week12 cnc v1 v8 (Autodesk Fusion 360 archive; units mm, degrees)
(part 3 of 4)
sketch "Sketch43" plane through (0, 0, 0) normal (0, 0, 1) x axis (1, 0, 0)
  line L1 (2935.833, 1472.2699) -> (497.833, 1472.2699)
  line L2 (497.833, 1472.2699) -> (497.833, 2691.2699)
  line L3 (497.833, 2691.2699) -> (2935.833, 2691.2699)
  line L4 (2935.833, 2691.2699) -> (2935.833, 1472.2699)
  line L5 (1708.427, 1904.6779) -> (1708.427, 1833.235)
  line L6 (1720.427, 1908.9564) -> (1712.7056, 1908.9564)
  line L7 (1720.427, 1971.9564) -> (1720.427, 1908.9564)
  line L8 (1684.7056, 1971.9564) -> (1720.427, 1971.9564)
  line L9 (1680.427, 1983.9564) -> (1680.427, 1976.235)
  line L10 (1626.7841, 1983.9564) -> (1680.427, 1983.9564)
  line L11 (1626.7841, 1976.235) -> (1626.7841, 1983.9564)
  line L12 (1591.0627, 1971.9564) -> (1622.5056, 1971.9564)
  line L13 (1586.7841, 1983.9564) -> (1586.7841, 1976.235)
  line L14 (1533.1413, 1983.9564) -> (1586.7841, 1983.9564)
  line L15 (1533.1413, 1976.235) -> (1533.1413, 1983.9564)
  line L16 (1497.4198, 1971.9564) -> (1528.8627, 1971.9564)
  line L17 (1493.1413, 1983.9564) -> (1493.1413, 1976.235)
  line L18 (1439.4984, 1983.9564) -> (1493.1413, 1983.9564)
  line L19 (1439.4984, 1976.235) -> (1439.4984, 1983.9564)
  line L20 (1403.777, 1971.9564) -> (1435.2199, 1971.9564)
  line L21 (1399.4984, 1983.9564) -> (1399.4984, 1976.235)
  line L22 (1345.8556, 1983.9564) -> (1399.4984, 1983.9564)
  line L23 (1345.8556, 1976.235) -> (1345.8556, 1983.9564)
  line L24 (1310.1341, 1971.9564) -> (1341.577, 1971.9564)
  line L25 (1305.8556, 1983.9564) -> (1305.8556, 1976.235)
  line L26 (1252.2127, 1983.9564) -> (1305.8556, 1983.9564)
  line L27 (1252.2127, 1976.235) -> (1252.2127, 1983.9564)
  line L28 (1216.4913, 1971.9564) -> (1247.9342, 1971.9564)
  line L29 (1212.2127, 1983.9564) -> (1212.2127, 1976.235)
  line L30 (1158.5699, 1983.9564) -> (1212.2127, 1983.9564)
  line L31 (1158.5699, 1976.235) -> (1158.5699, 1983.9564)
  line L32 (1122.8484, 1971.9564) -> (1154.2913, 1971.9564)
  line L33 (1118.5699, 1983.9564) -> (1118.5699, 1976.235)
  line L34 (1064.927, 1983.9564) -> (1118.5699, 1983.9564)
  line L35 (1064.927, 1976.235) -> (1064.927, 1983.9564)
  line L36 (1025, 1971.9564) -> (1060.6484, 1971.9564)
  line L37 (1025, 1908.9564) -> (1025, 1971.9564)
  line L38 (1032.7214, 1908.9564) -> (1025, 1908.9564)
  line L39 (1037, 1833.235) -> (1037, 1904.6779)
  line L40 (1025, 1828.9564) -> (1032.7214, 1828.9564)
  line L41 (1025, 1688.9564) -> (1025, 1828.9564)
  line L42 (1032.7214, 1688.9564) -> (1025, 1688.9564)
  line L43 (1037, 1613.235) -> (1037, 1684.6779)
  line L44 (1025, 1608.9564) -> (1032.7214, 1608.9564)
  line L45 (1025, 1545.9564) -> (1025, 1608.9564)
  line L46 (1060.6484, 1545.9564) -> (1025, 1545.9564)
  line L47 (1064.927, 1533.9564) -> (1064.927, 1541.6779)
  line L48 (1118.5699, 1533.9564) -> (1064.927, 1533.9564)
  line L49 (1118.5699, 1541.6779) -> (1118.5699, 1533.9564)
  line L50 (1154.2913, 1545.9564) -> (1122.8484, 1545.9564)
  line L51 (1158.5699, 1533.9564) -> (1158.5699, 1541.6779)
  line L52 (1212.2127, 1533.9564) -> (1158.5699, 1533.9564)
  line L53 (1212.2127, 1541.6779) -> (1212.2127, 1533.9564)
  line L54 (1247.9342, 1545.9564) -> (1216.4913, 1545.9564)
  line L55 (1252.2127, 1533.9564) -> (1252.2127, 1541.6779)
  line L56 (1305.8556, 1533.9564) -> (1252.2127, 1533.9564)
  line L57 (1305.8556, 1541.6779) -> (1305.8556, 1533.9564)
  line L58 (1341.577, 1545.9564) -> (1310.1341, 1545.9564)
  line L59 (1345.8556, 1533.9564) -> (1345.8556, 1541.6779)
  line L60 (1399.4984, 1533.9564) -> (1345.8556, 1533.9564)
  line L61 (1399.4984, 1541.6779) -> (1399.4984, 1533.9564)
  line L62 (1435.2199, 1545.9564) -> (1403.777, 1545.9564)
  line L63 (1439.4984, 1533.9564) -> (1439.4984, 1541.6779)
  line L64 (1493.1413, 1533.9564) -> (1439.4984, 1533.9564)
  line L65 (1493.1413, 1541.6779) -> (1493.1413, 1533.9564)
  line L66 (1528.8627, 1545.9564) -> (1497.4198, 1545.9564)
  line L67 (1533.1413, 1533.9564) -> (1533.1413, 1541.6779)
  line L68 (1586.7841, 1533.9564) -> (1533.1413, 1533.9564)
  line L69 (1586.7841, 1541.6779) -> (1586.7841, 1533.9564)
  line L70 (1622.5056, 1545.9564) -> (1591.0627, 1545.9564)
  line L71 (1626.7841, 1533.9564) -> (1626.7841, 1541.6779)
  line L72 (1680.427, 1533.9564) -> (1626.7841, 1533.9564)
  line L73 (1680.427, 1541.6779) -> (1680.427, 1533.9564)
  line L74 (1720.427, 1545.9564) -> (1684.7056, 1545.9564)
  line L75 (1720.427, 1608.9564) -> (1720.427, 1545.9564)
  line L76 (1712.7056, 1608.9564) -> (1720.427, 1608.9564)
  line L77 (1708.427, 1684.6779) -> (1708.427, 1613.235)
  line L78 (1720.427, 1688.9564) -> (1712.7056, 1688.9564)
  line L79 (1720.427, 1828.9564) -> (1720.427, 1688.9564)
  line L80 (1712.7056, 1828.9564) -> (1720.427, 1828.9564)
  line L81 (1115.4563, 2086.0154) -> (1140.8241, 2086.0245)
  line L82 (1115.4588, 2079.0154) -> (1115.4563, 2086.0154)
  line L83 (1126.028, 2060.7242) -> (1115.4588, 2079.0154)
  line L84 (1075.6843, 2104.8848) -> (1050.3269, 2104.8893)
  line L85 (1075.6855, 2111.8848) -> (1075.6843, 2104.8848)
  line L86 (1065.1198, 2130.1926) -> (1075.6855, 2111.8848)
  line L87 (1669.8875, 2111.8848) -> (1680.4532, 2130.1927)
  line L88 (1669.8887, 2104.8848) -> (1669.8875, 2111.8848)
  line L89 (1695.2462, 2104.8893) -> (1669.8887, 2104.8848)
  line L90 (1630.1142, 2079.0154) -> (1619.545, 2060.7243)
  line L91 (1630.1167, 2086.0154) -> (1630.1142, 2079.0154)
  line L92 (1604.749, 2086.0245) -> (1630.1167, 2086.0154)
  line L93 (1708.5, 2069.9288) -> (1708.5, 2038.4859)
  line L94 (1720.5, 2074.2073) -> (1712.7786, 2074.2073)
  line L95 (1720.5, 2095.4582) -> (1720.5, 2074.2073)
  line L96 (1544.8686, 2165.9601) -> (1649.9982, 2165.9601)
  line L97 (1267.7865, 2115.9601) -> (1477.7865, 2115.9601)
  line L98 (1095.5749, 2165.9601) -> (1200.7045, 2165.9601)
  line L99 (1025.0731, 2074.2073) -> (1025.0731, 2095.4582)
  line L100 (1032.7944, 2074.2073) -> (1025.0731, 2074.2073)
  line L101 (1037.073, 2038.4859) -> (1037.073, 2069.9288)
  line L102 (1025.0731, 2034.2073) -> (1032.7944, 2034.2073)
  line L103 (1025.0731, 2029.235) -> (1025.0731, 2034.2073)
  line L104 (1025, 2012.9564) -> (1025, 2024.8857)
  line L105 (1065, 2012.9564) -> (1025, 2012.9564)
  line L106 (1065, 2020.6778) -> (1065, 2012.9564)
  line L107 (1114.3643, 2024.9564) -> (1069.2786, 2024.9564)
  line L108 (1118.6429, 2012.9564) -> (1118.6429, 2020.6778)
  line L109 (1158.6429, 2012.9564) -> (1118.6429, 2012.9564)
  line L110 (1158.6429, 2020.6778) -> (1158.6429, 2012.9564)
  line L111 (1208.0072, 2024.9564) -> (1162.9214, 2024.9564)
  line L112 (1212.2857, 2012.9564) -> (1212.2857, 2020.6778)
  line L113 (1252.2857, 2012.9564) -> (1212.2857, 2012.9564)
  line L114 (1252.2857, 2020.6778) -> (1252.2857, 2012.9564)
  line L115 (1301.65, 2024.9564) -> (1256.5643, 2024.9564)
  line L116 (1305.9286, 2012.9564) -> (1305.9286, 2020.6778)
  line L117 (1345.9286, 2012.9564) -> (1305.9286, 2012.9564)
  line L118 (1345.9286, 2020.6778) -> (1345.9286, 2012.9564)
  line L119 (1395.2929, 2024.9564) -> (1350.2071, 2024.9564)
  line L120 (1399.5714, 2012.9564) -> (1399.5714, 2020.6778)
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sketch "Sketch44" plane through (0, 0, 0) normal (0, 0, 1) x axis (1, 0, 0)
  line L1 (1708.427, 1904.6779) -> (1708.427, 1833.235)
  line L2 (1720.427, 1908.9564) -> (1712.7056, 1908.9564)
  line L3 (1720.427, 1971.9564) -> (1720.427, 1908.9564)
  line L4 (1684.7056, 1971.9564) -> (1720.427, 1971.9564)
  line L5 (1680.427, 1983.9564) -> (1680.427, 1976.235)
  line L6 (1626.7841, 1983.9564) -> (1680.427, 1983.9564)
  line L7 (1626.7841, 1976.235) -> (1626.7841, 1983.9564)
  line L8 (1591.0627, 1971.9564) -> (1622.5056, 1971.9564)
  line L9 (1586.7841, 1983.9564) -> (1586.7841, 1976.235)
  line L10 (1533.1413, 1983.9564) -> (1586.7841, 1983.9564)
  line L11 (1533.1413, 1976.235) -> (1533.1413, 1983.9564)
  line L12 (1497.4198, 1971.9564) -> (1528.8627, 1971.9564)
  line L13 (1493.1413, 1983.9564) -> (1493.1413, 1976.235)
  line L14 (1439.4984, 1983.9564) -> (1493.1413, 1983.9564)
  line L15 (1439.4984, 1976.235) -> (1439.4984, 1983.9564)
  line L16 (1403.777, 1971.9564) -> (1435.2199, 1971.9564)
  line L17 (1399.4984, 1983.9564) -> (1399.4984, 1976.235)
  line L18 (1345.8556, 1983.9564) -> (1399.4984, 1983.9564)
  line L19 (1345.8556, 1976.235) -> (1345.8556, 1983.9564)
  line L20 (1310.1341, 1971.9564) -> (1341.577, 1971.9564)
  line L21 (1305.8556, 1983.9564) -> (1305.8556, 1976.235)
  line L22 (1252.2127, 1983.9564) -> (1305.8556, 1983.9564)
  line L23 (1252.2127, 1976.235) -> (1252.2127, 1983.9564)
  line L24 (1216.4913, 1971.9564) -> (1247.9342, 1971.9564)
  line L25 (1212.2127, 1983.9564) -> (1212.2127, 1976.235)
  line L26 (1158.5699, 1983.9564) -> (1212.2127, 1983.9564)
  line L27 (1158.5699, 1976.235) -> (1158.5699, 1983.9564)
  line L28 (1122.8484, 1971.9564) -> (1154.2913, 1971.9564)
  line L29 (1118.5699, 1983.9564) -> (1118.5699, 1976.235)
  line L30 (1064.927, 1983.9564) -> (1118.5699, 1983.9564)
  line L31 (1064.927, 1976.235) -> (1064.927, 1983.9564)
  line L32 (1025, 1971.9564) -> (1060.6484, 1971.9564)
  line L33 (1025, 1908.9564) -> (1025, 1971.9564)
  line L34 (1032.7214, 1908.9564) -> (1025, 1908.9564)
  line L35 (1037, 1833.235) -> (1037, 1904.6779)
  line L36 (1025, 1828.9564) -> (1032.7214, 1828.9564)
  line L37 (1025, 1688.9564) -> (1025, 1828.9564)
  line L38 (1032.7214, 1688.9564) -> (1025, 1688.9564)
  line L39 (1037, 1613.235) -> (1037, 1684.6779)
  line L40 (1025, 1608.9564) -> (1032.7214, 1608.9564)
  line L41 (1025, 1545.9564) -> (1025, 1608.9564)
  line L42 (1060.6484, 1545.9564) -> (1025, 1545.9564)
  line L43 (1064.927, 1533.9564) -> (1064.927, 1541.6779)
  line L44 (1118.5699, 1533.9564) -> (1064.927, 1533.9564)
  line L45 (1118.5699, 1541.6779) -> (1118.5699, 1533.9564)
  line L46 (1154.2913, 1545.9564) -> (1122.8484, 1545.9564)
  line L47 (1158.5699, 1533.9564) -> (1158.5699, 1541.6779)
  line L48 (1212.2127, 1533.9564) -> (1158.5699, 1533.9564)
  line L49 (1212.2127, 1541.6779) -> (1212.2127, 1533.9564)
  line L50 (1247.9342, 1545.9564) -> (1216.4913, 1545.9564)
  line L51 (1252.2127, 1533.9564) -> (1252.2127, 1541.6779)
  line L52 (1305.8556, 1533.9564) -> (1252.2127, 1533.9564)
  line L53 (1305.8556, 1541.6779) -> (1305.8556, 1533.9564)
  line L54 (1341.577, 1545.9564) -> (1310.1341, 1545.9564)
  line L55 (1345.8556, 1533.9564) -> (1345.8556, 1541.6779)
  line L56 (1399.4984, 1533.9564) -> (1345.8556, 1533.9564)
  line L57 (1399.4984, 1541.6779) -> (1399.4984, 1533.9564)
  line L58 (1435.2199, 1545.9564) -> (1403.777, 1545.9564)
  line L59 (1439.4984, 1533.9564) -> (1439.4984, 1541.6779)
  line L60 (1493.1413, 1533.9564) -> (1439.4984, 1533.9564)
  line L61 (1493.1413, 1541.6779) -> (1493.1413, 1533.9564)
  line L62 (1528.8627, 1545.9564) -> (1497.4198, 1545.9564)
  line L63 (1533.1413, 1533.9564) -> (1533.1413, 1541.6779)
  line L64 (1586.7841, 1533.9564) -> (1533.1413, 1533.9564)
  line L65 (1586.7841, 1541.6779) -> (1586.7841, 1533.9564)
  line L66 (1622.5056, 1545.9564) -> (1591.0627, 1545.9564)
  line L67 (1626.7841, 1533.9564) -> (1626.7841, 1541.6779)
  line L68 (1680.427, 1533.9564) -> (1626.7841, 1533.9564)
  line L69 (1680.427, 1541.6779) -> (1680.427, 1533.9564)
  line L70 (1720.427, 1545.9564) -> (1684.7056, 1545.9564)
  line L71 (1720.427, 1608.9564) -> (1720.427, 1545.9564)
  line L72 (1712.7056, 1608.9564) -> (1720.427, 1608.9564)
  line L73 (1708.427, 1684.6779) -> (1708.427, 1613.235)
  line L74 (1720.427, 1688.9564) -> (1712.7056, 1688.9564)
  line L75 (1720.427, 1828.9564) -> (1720.427, 1688.9564)
  line L76 (1712.7056, 1828.9564) -> (1720.427, 1828.9564)
  line L77 (1763.427, 1816.9583) -> (1763.427, 1721.9583)
  line L78 (1763.427, 1816.9583) -> (1763.427, 1721.9583)
  line L79 (1754.427, 1816.9583) -> (1759.1484, 1816.9583)
  line L80 (1749.427, 1726.9583) -> (1749.427, 1811.9583)
  line L81 (1759.1484, 1721.9583) -> (1754.427, 1721.9583)
  line L82 (2185.427, 1833.9564) -> (2185.427, 1821.2368)
  line L83 (1763.427, 1833.9564) -> (2185.427, 1833.9564)
  line L84 (1763.427, 1821.2368) -> (1763.427, 1833.9564)
  line L85 (1763.427, 1721.9583) -> (1763.427, 1816.9583)
  line L86 (1763.427, 1548.9564) -> (1763.427, 1717.6797)
  line L87 (1836.055, 1533.9564) -> (1778.427, 1533.9564)
  line L88 (2170.427, 1533.9564) -> (2112.5225, 1533.9564)
  line L89 (2185.427, 1717.6797) -> (2185.427, 1548.9564)
  line L90 (2185.427, 1816.9583) -> (2185.427, 1721.9583)
  arc A1 centre (1710.5663, 1831.0957) radius 3.0254 clockwise from (1712.7056, 1828.9564) to (1708.427, 1833.235)
  arc A2 centre (1710.5663, 1906.8171) radius 3.0254 clockwise from (1708.427, 1904.6779) to (1712.7056, 1908.9564)
  arc A3 centre (1682.5663, 1974.0957) radius 3.0254 clockwise from (1684.7056, 1971.9564) to (1680.427, 1976.235)
  arc A4 centre (1624.6449, 1974.0957) radius 3.0254 clockwise from (1626.7841, 1976.235) to (1622.5056, 1971.9564)
  arc A5 centre (1588.9234, 1974.0957) radius 3.0254 clockwise from (1591.0627, 1971.9564) to (1586.7841, 1976.235)
  arc A6 centre (1531.002, 1974.0957) radius 3.0254 clockwise from (1533.1413, 1976.235) to (1528.8627, 1971.9564)
  arc A7 centre (1495.2806, 1974.0957) radius 3.0254 clockwise from (1497.4198, 1971.9564) to (1493.1413, 1976.235)
  arc A8 centre (1437.3591, 1974.0957) radius 3.0254 clockwise from (1439.4984, 1976.235) to (1435.2199, 1971.9564)
  arc A9 centre (1401.6377, 1974.0957) radius 3.0254 clockwise from (1403.777, 1971.9564) to (1399.4984, 1976.235)
  arc A10 centre (1343.7163, 1974.0957) radius 3.0254 clockwise from (1345.8556, 1976.235) to (1341.577, 1971.9564)
  arc A11 centre (1307.9949, 1974.0957) radius 3.0254 clockwise from (1310.1341, 1971.9564) to (1305.8556, 1976.235)
  arc A12 centre (1250.0734, 1974.0957) radius 3.0254 clockwise from (1252.2127, 1976.235) to (1247.9342, 1971.9564)
  arc A13 centre (1214.352, 1974.0957) radius 3.0254 clockwise from (1216.4913, 1971.9564) to (1212.2127, 1976.235)
  arc A14 centre (1156.4306, 1974.0957) radius 3.0254 clockwise from (1158.5699, 1976.235) to (1154.2913, 1971.9564)
  arc A15 centre (1120.7091, 1974.0957) radius 3.0254 clockwise from (1122.8484, 1971.9564) to (1118.5699, 1976.235)
  arc A16 centre (1062.7877, 1974.0957) radius 3.0254 clockwise from (1064.927, 1976.235) to (1060.6484, 1971.9564)
  arc A17 centre (1034.8607, 1906.8171) radius 3.0254 clockwise from (1032.7214, 1908.9564) to (1037, 1904.6779)
  arc A18 centre (1034.8607, 1831.0957) radius 3.0254 clockwise from (1037, 1833.235) to (1032.7214, 1828.9564)
  arc A19 centre (1034.8607, 1686.8171) radius 3.0254 clockwise from (1032.7214, 1688.9564) to (1037, 1684.6779)
  arc A20 centre (1034.8607, 1611.0957) radius 3.0254 clockwise from (1037, 1613.235) to (1032.7214, 1608.9564)
  arc A21 centre (1062.7877, 1543.8171) radius 3.0254 clockwise from (1060.6484, 1545.9564) to (1064.927, 1541.6779)
  arc A22 centre (1120.7091, 1543.8171) radius 3.0254 clockwise from (1118.5699, 1541.6779) to (1122.8484, 1545.9564)
  arc A23 centre (1156.4306, 1543.8171) radius 3.0254 clockwise from (1154.2913, 1545.9564) to (1158.5699, 1541.6779)
  arc A24 centre (1214.352, 1543.8171) radius 3.0254 clockwise from (1212.2127, 1541.6779) to (1216.4913, 1545.9564)
  arc A25 centre (1250.0734, 1543.8171) radius 3.0254 clockwise from (1247.9342, 1545.9564) to (1252.2127, 1541.6779)
  arc A26 centre (1307.9949, 1543.8171) radius 3.0254 clockwise from (1305.8556, 1541.6779) to (1310.1341, 1545.9564)
  arc A27 centre (1343.7163, 1543.8171) radius 3.0254 clockwise from (1341.577, 1545.9564) to (1345.8556, 1541.6779)
  arc A28 centre (1401.6377, 1543.8171) radius 3.0254 clockwise from (1399.4984, 1541.6779) to (1403.777, 1545.9564)
  arc A29 centre (1437.3591, 1543.8171) radius 3.0254 clockwise from (1435.2199, 1545.9564) to (1439.4984, 1541.6779)
  arc A30 centre (1495.2806, 1543.8171) radius 3.0254 clockwise from (1493.1413, 1541.6779) to (1497.4198, 1545.9564)
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sketch "sideleft1" plane through (0, 0, -20) normal (0, 0, 1) x axis (-1, 0, 0)
  line L1 (-1115.4563, -2086.0154) -> (-1140.8241, -2086.0245)
  line L2 (-1115.4588, -2079.0154) -> (-1115.4563, -2086.0154)
  line L3 (-1126.028, -2060.7242) -> (-1115.4588, -2079.0154)
  line L4 (-1075.6843, -2104.8848) -> (-1050.327, -2104.8893)
  line L5 (-1075.6855, -2111.8848) -> (-1075.6843, -2104.8848)
  line L6 (-1065.1199, -2130.1926) -> (-1075.6855, -2111.8848)
  line L7 (-1669.8875, -2111.8848) -> (-1680.4532, -2130.1927)
  line L8 (-1669.8888, -2104.8848) -> (-1669.8875, -2111.8848)
  line L9 (-1695.2462, -2104.8893) -> (-1669.8888, -2104.8848)
  line L10 (-1630.1142, -2079.0154) -> (-1619.5451, -2060.7243)
  line L11 (-1630.1168, -2086.0154) -> (-1630.1142, -2079.0154)
  line L12 (-1604.749, -2086.0245) -> (-1630.1168, -2086.0154)
  line L13 (-1708.5, -2069.9288) -> (-1708.5, -2038.4859)
  line L14 (-1720.5, -2074.2073) -> (-1712.7786, -2074.2073)
  line L15 (-1720.5, -2095.4582) -> (-1720.5, -2074.2073)
  line L16 (-1544.8686, -2165.9601) -> (-1649.9982, -2165.9601)
  line L17 (-1267.7866, -2115.9601) -> (-1477.7866, -2115.9601)
  line L18 (-1095.575, -2165.9601) -> (-1200.7045, -2165.9601)
  line L19 (-1025.0731, -2074.2073) -> (-1025.0731, -2095.4582)
  line L20 (-1032.7945, -2074.2073) -> (-1025.0731, -2074.2073)
  line L21 (-1037.073, -2038.4859) -> (-1037.073, -2069.9288)
  line L22 (-1025.0731, -2034.2073) -> (-1032.7945, -2034.2073)
  line L23 (-1025.0731, -2029.235) -> (-1025.0731, -2034.2073)
  line L24 (-1025, -2012.9564) -> (-1025, -2024.8857)
  line L25 (-1065, -2012.9564) -> (-1025, -2012.9564)
  line L26 (-1065, -2020.6778) -> (-1065, -2012.9564)
  line L27 (-1114.3643, -2024.9564) -> (-1069.2786, -2024.9564)
  line L28 (-1118.6429, -2012.9564) -> (-1118.6429, -2020.6778)
  line L29 (-1158.6429, -2012.9564) -> (-1118.6429, -2012.9564)
  line L30 (-1158.6429, -2020.6778) -> (-1158.6429, -2012.9564)
  line L31 (-1208.0072, -2024.9564) -> (-1162.9214, -2024.9564)
  line L32 (-1212.2857, -2012.9564) -> (-1212.2857, -2020.6778)
  line L33 (-1252.2857, -2012.9564) -> (-1212.2857, -2012.9564)
  line L34 (-1252.2857, -2020.6778) -> (-1252.2857, -2012.9564)
  line L35 (-1301.65, -2024.9564) -> (-1256.5643, -2024.9564)
  line L36 (-1305.9286, -2012.9564) -> (-1305.9286, -2020.6778)
  line L37 (-1345.9286, -2012.9564) -> (-1305.9286, -2012.9564)
  line L38 (-1345.9286, -2020.6778) -> (-1345.9286, -2012.9564)
  line L39 (-1395.2929, -2024.9564) -> (-1350.2072, -2024.9564)
  line L40 (-1399.5715, -2012.9564) -> (-1399.5715, -2020.6778)
  line L41 (-1439.5715, -2012.9564) -> (-1399.5715, -2012.9564)
  line L42 (-1439.5715, -2020.6778) -> (-1439.5715, -2012.9564)
  line L43 (-1488.9358, -2024.9564) -> (-1443.85, -2024.9564)
  line L44 (-1493.2143, -2012.9564) -> (-1493.2143, -2020.6778)
  line L45 (-1533.2143, -2012.9564) -> (-1493.2143, -2012.9564)
  line L46 (-1533.2143, -2020.6778) -> (-1533.2143, -2012.9564)
  line L47 (-1582.5786, -2024.9564) -> (-1537.4929, -2024.9564)
  line L48 (-1586.8572, -2012.9564) -> (-1586.8572, -2020.6778)
  line L49 (-1626.8572, -2012.9564) -> (-1586.8572, -2012.9564)
  line L50 (-1626.8572, -2020.6778) -> (-1626.8572, -2012.9564)
  line L51 (-1676.2215, -2024.9564) -> (-1631.1357, -2024.9564)
  line L52 (-1680.5, -2012.9564) -> (-1680.5, -2020.6778)
  line L53 (-1720.5, -2012.9564) -> (-1680.5, -2012.9564)
  line L54 (-1720.5, -2034.2073) -> (-1720.5, -2012.9564)
  line L55 (-1712.7786, -2034.2073) -> (-1720.5, -2034.2073)
  line L56 (-1371.0651, -2047.6541) -> (-1374.508, -2047.6541)
  line L57 (-1366.7865, -2083.3755) -> (-1366.7865, -2051.9327)
  line L58 (-1374.508, -2087.6541) -> (-1371.0651, -2087.6541)
  line L59 (-1378.7865, -2051.9327) -> (-1378.7865, -2083.3755)
  arc A1 centre (-1066.1647, -2133.0318) radius 3.0254 clockwise from (-1065.1199, -2130.1926) to (-1066.38, -2136.0496)
  arc A2 centre (-1095.575, -2095.4582) radius 50 clockwise from (-1066.38, -2136.0496) to (-1145.2783, -2090.0192)
  arc A3 centre (-1142.7498, -2088.3579) radius 3.0254 clockwise from (-1145.2783, -2090.0192) to (-1140.8241, -2086.0245)
  arc A4 centre (-1124.9854, -2057.8841) radius 3.0254 clockwise from (-1126.028, -2060.7242) to (-1124.7693, -2054.8665)
  arc A5 centre (-1095.575, -2095.4582) radius 50 clockwise from (-1124.7693, -2054.8665) to (-1045.8715, -2100.8953)
  arc A6 centre (-1048.3994, -2102.5575) radius 3.0254 clockwise from (-1045.8715, -2100.8953) to (-1050.327, -2104.8893)
  arc A7 centre (-1679.4083, -2133.0319) radius 3.0254 clockwise from (-1679.193, -2136.0496) to (-1680.4532, -2130.1927)
  arc A8 centre (-1697.1738, -2102.5575) radius 3.0254 clockwise from (-1695.2462, -2104.8893) to (-1699.7017, -2100.8953)
  arc A9 centre (-1649.9982, -2095.4582) radius 50 clockwise from (-1699.7017, -2100.8953) to (-1620.8038, -2054.8665)
  arc A10 centre (-1620.5877, -2057.8842) radius 3.0254 clockwise from (-1620.8038, -2054.8665) to (-1619.5451, -2060.7243)
  arc A11 centre (-1602.8233, -2088.3579) radius 3.0254 clockwise from (-1604.749, -2086.0245) to (-1600.2949, -2090.0192)
  arc A12 centre (-1649.9982, -2095.4582) radius 50 clockwise from (-1600.2949, -2090.0192) to (-1679.193, -2136.0496)
  arc A13 centre (-1710.6393, -2036.3466) radius 3.0254 clockwise from (-1712.7786, -2034.2073) to (-1708.5, -2038.4859)
  arc A14 centre (-1710.6393, -2072.068) radius 3.0254 clockwise from (-1708.5, -2069.9288) to (-1712.7786, -2074.2073)
  arc A15 centre (-1649.9982, -2095.4582) radius 70.5018 clockwise from (-1649.9982, -2165.9601) to (-1720.5, -2095.4582)
  arc A16 centre (-1544.8686, -2145.9601) radius 20 clockwise from (-1525.7023, -2151.6744) to (-1544.8686, -2165.9601)
  arc A17 centre (-1477.7866, -2165.9601) radius 50 clockwise from (-1525.7023, -2151.6744) to (-1477.7866, -2115.9601)
  arc A18 centre (-1267.7866, -2165.9601) radius 50 clockwise from (-1267.7866, -2115.9601) to (-1219.8708, -2151.6744)
  arc A19 centre (-1200.7045, -2145.9601) radius 20 clockwise from (-1200.7045, -2165.9601) to (-1219.8708, -2151.6744)
  arc A20 centre (-1095.575, -2095.4582) radius 70.5018 clockwise from (-1025.0731, -2095.4582) to (-1095.575, -2165.9601)
  arc A21 centre (-1034.9337, -2072.068) radius 3.0254 clockwise from (-1032.7945, -2074.2073) to (-1037.073, -2069.9288)
  arc A22 centre (-1034.9337, -2036.3466) radius 3.0254 clockwise from (-1037.073, -2038.4859) to (-1032.7945, -2034.2073)
  arc A23 centre (-1022.9338, -2027.0957) radius 3.0254 clockwise from (-1025.0731, -2029.235) to (-1025, -2024.8857)
  arc A24 centre (-1067.1393, -2022.8171) radius 3.0254 clockwise from (-1065, -2020.6778) to (-1069.2786, -2024.9564)
  arc A25 centre (-1116.5036, -2022.8171) radius 3.0254 clockwise from (-1114.3643, -2024.9564) to (-1118.6429, -2020.6778)
  arc A26 centre (-1160.7822, -2022.8171) radius 3.0254 clockwise from (-1158.6429, -2020.6778) to (-1162.9214, -2024.9564)
  arc A27 centre (-1210.1465, -2022.8171) radius 3.0254 clockwise from (-1208.0072, -2024.9564) to (-1212.2857, -2020.6778)
  arc A28 centre (-1254.425, -2022.8171) radius 3.0254 clockwise from (-1252.2857, -2020.6778) to (-1256.5643, -2024.9564)
  arc A29 centre (-1303.7893, -2022.8171) radius 3.0254 clockwise from (-1301.65, -2024.9564) to (-1305.9286, -2020.6778)
  arc A30 centre (-1348.0679, -2022.8171) radius 3.0254 clockwise from (-1345.9286, -2020.6778) to (-1350.2072, -2024.9564)
  arc A31 centre (-1397.4322, -2022.8171) radius 3.0254 clockwise from (-1395.2929, -2024.9564) to (-1399.5715, -2020.6778)
  arc A32 centre (-1441.7107, -2022.8171) radius 3.0254 clockwise from (-1439.5715, -2020.6778) to (-1443.85, -2024.9564)
  arc A33 centre (-1491.075, -2022.8171) radius 3.0254 clockwise from (-1488.9358, -2024.9564) to (-1493.2143, -2020.6778)
  arc A34 centre (-1535.3536, -2022.8171) radius 3.0254 clockwise from (-1533.2143, -2020.6778) to (-1537.4929, -2024.9564)
  arc A35 centre (-1584.7179, -2022.8171) radius 3.0254 clockwise from (-1582.5786, -2024.9564) to (-1586.8572, -2020.6778)
  arc A36 centre (-1628.9965, -2022.8171) radius 3.0254 clockwise from (-1626.8572, -2020.6778) to (-1631.1357, -2024.9564)
  arc A37 centre (-1678.3607, -2022.8171) radius 3.0254 clockwise from (-1676.2215, -2024.9564) to (-1680.5, -2020.6778)
  arc A38 centre (-1376.6472, -2049.7934) radius 3.0254 clockwise from (-1378.7865, -2051.9327) to (-1374.508, -2047.6541)
  arc A39 centre (-1368.9258, -2049.7934) radius 3.0254 clockwise from (-1371.0651, -2047.6541) to (-1366.7865, -2051.9327)
  arc A40 centre (-1368.9258, -2085.5148) radius 3.0254 clockwise from (-1366.7865, -2083.3755) to (-1371.0651, -2087.6541)
  arc A41 centre (-1376.6472, -2085.5148) radius 3.0254 clockwise from (-1374.508, -2087.6541) to (-1378.7865, -2083.3755)
sketch "left2" plane through (0, 0, -20) normal (0, 0, 1) x axis (-1, 0, 0)
  line L1 (-1502, -2517.033) -> (-1502, -2522.0053)
  line L2 (-1560.7215, -2517.033) -> (-1502, -2517.033)
  line L3 (-1565, -2505.033) -> (-1565, -2512.7544)
  line L4 (-1645, -2505.033) -> (-1565, -2505.033)
  line L5 (-1645, -2512.7544) -> (-1645, -2505.033)
  line L6 (-1780.7215, -2517.033) -> (-1649.2786, -2517.033)
  line L7 (-1785, -2505.033) -> (-1785, -2512.7544)
  line L8 (-1865, -2505.033) -> (-1785, -2505.033)
  line L9 (-1865, -2512.7544) -> (-1865, -2505.033)
  line L10 (-1928, -2517.033) -> (-1869.2786, -2517.033)
  line L11 (-1928, -2522.0053) -> (-1928, -2517.033)
  line L12 (-1940, -2526.2839) -> (-1932.2786, -2526.2839)
  line L13 (-1940, -2566.2839) -> (-1940, -2526.2839)
  line L14 (-1932.2786, -2566.2839) -> (-1940, -2566.2839)
  line L15 (-1928, -2576.2839) -> (-1928, -2570.5624)
  line L16 (-1502, -2576.2839) -> (-1928, -2576.2839)
  line L17 (-1502, -2570.5624) -> (-1502, -2576.2839)
  line L18 (-1490, -2566.2839) -> (-1497.7215, -2566.2839)
  line L19 (-1490, -2526.2839) -> (-1490, -2566.2839)
  line L20 (-1497.7215, -2526.2839) -> (-1490, -2526.2839)
  arc A1 centre (-1499.8607, -2524.1446) radius 3.0254 clockwise from (-1497.7215, -2526.2839) to (-1502, -2522.0053)
  arc A2 centre (-1562.8607, -2514.8937) radius 3.0254 clockwise from (-1560.7215, -2517.033) to (-1565, -2512.7544)
  arc A3 centre (-1647.1393, -2514.8937) radius 3.0254 clockwise from (-1645, -2512.7544) to (-1649.2786, -2517.033)
  arc A4 centre (-1782.8607, -2514.8937) radius 3.0254 clockwise from (-1780.7215, -2517.033) to (-1785, -2512.7544)
  arc A5 centre (-1867.1393, -2514.8937) radius 3.0254 clockwise from (-1865, -2512.7544) to (-1869.2786, -2517.033)
  arc A6 centre (-1930.1393, -2524.1446) radius 3.0254 clockwise from (-1928, -2522.0053) to (-1932.2786, -2526.2839)
  arc A7 centre (-1930.1393, -2568.4232) radius 3.0254 clockwise from (-1932.2786, -2566.2839) to (-1928, -2570.5624)
  arc A8 centre (-1499.8607, -2568.4232) radius 3.0254 clockwise from (-1502, -2570.5624) to (-1497.7215, -2566.2839)
sketch "left3" plane through (0, 0, -20) normal (0, 0, 1) x axis (1, 0, 0)
  line L1 (1928, 2668.088) -> (1928, 2657.3665)
  line L2 (1502, 2668.088) -> (1928, 2668.088)
  line L3 (1502, 2657.3665) -> (1502, 2668.088)
  line L4 (1490, 2653.088) -> (1497.7214, 2653.088)
  line L5 (1490, 2613.088) -> (1490, 2653.088)
  line L6 (1497.7214, 2613.088) -> (1490, 2613.088)
  line L7 (1502, 2605.2838) -> (1502, 2608.8094)
  line L8 (1928, 2605.2838) -> (1502, 2605.2838)
  line L9 (1928, 2608.8094) -> (1928, 2605.2838)
  line L10 (1940, 2613.088) -> (1932.2786, 2613.088)
  line L11 (1940, 2653.088) -> (1940, 2613.088)
  line L12 (1932.2786, 2653.088) -> (1940, 2653.088)
  arc A1 centre (1930.1393, 2655.2273) radius 3.0254 clockwise from (1932.2786, 2653.088) to (1928, 2657.3665)
  arc A2 centre (1499.8607, 2655.2273) radius 3.0254 clockwise from (1502, 2657.3665) to (1497.7214, 2653.088)
  arc A3 centre (1499.8607, 2610.9487) radius 3.0254 clockwise from (1497.7214, 2613.088) to (1502, 2608.8094)
  arc A4 centre (1930.1393, 2610.9487) radius 3.0254 clockwise from (1928, 2608.8094) to (1932.2786, 2613.088)
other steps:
base_feature "Base Feature1"
base_feature "Base Feature1"
base_feature "Base Feature1"
base_feature "Base Feature1"
base_feature "Base Feature1"
base_feature "Base Feature1"
base_feature "Base Feature1"
base_feature "Base Feature1" bodies "Body1 (1) (1)"
base_feature "Base Feature1"
base_feature "Base Feature1"
derived_base_feature "Derived Base Feature1" bodies "wall0"
derived_base_feature "Derived Base Feature1" bodies "wall2"
fillet "Fillet2" radius 3 named "d6_1"
fillet "Fillet1" radius 15
derived_base_feature "Derived Base Feature1" bodies "wall1"
base_feature "Base Feature1"
base_feature "Base Feature1"
base_feature "Base Feature1"
base_feature "Base Feature1"
base_feature "Base Feature1"
base_feature "Base Feature1"
base_feature "Base Feature1"
derived_base_feature "Derived Base Feature1"
base_feature "Base Feature1"
derived_base_feature "Derived Base Feature1" bodies "Body1 (1)"
derived_base_feature "Derived Base Feature1"
base_feature "Base Feature3"
base_feature "Base Feature4" bodies "Body1 (1)", "Body1 (1) (1)"
create_component "CreateComponent8"
create_component "CreateComponent9"
create_component "CreateComponent10"
create_component "CreateComponent11"
create_component "CreateComponent12"
joint_origin "JointOrigin1"
joint_origin "JointOrigin1"
joint_origin "JointOrigin2"
joint_origin "JointOrigin2"
create_component "CreateComponent13"
remove_body "RemoveBody4"
create_component "CreateComponent14"
remove_body "RemoveBody5"
create_component "CreateComponent15"
remove_body "RemoveBody6"
create_component "CreateComponent16"
remove_body "RemoveBody7"
create_component "CreateComponent17"
remove_body "RemoveBody8"
create_component "CreateComponent18"
remove_body "RemoveBody9"
create_component "CreateComponent19"
remove_body "RemoveBody10"
create_component "CreateComponent20"
remove_body "RemoveBody11"
remove_body "RemoveBody1"
remove_body "RemoveBody1"
remove_body "RemoveBody1"
remove_body "RemoveBody1"
remove_body "RemoveBody2"
remove_body "RemoveBody2"
remove_body "RemoveBody2"
remove_body "RemoveBody2"
create_component "CreateComponent1"
remove_body "RemoveBody1"
create_component "CreateComponent2"
remove_body "RemoveBody2"
create_component "CreateComponent1"
remove_body "RemoveBody1"
create_component "CreateComponent2"
remove_body "RemoveBody2"
create_component "CreateComponent39"
remove_body "RemoveBody21"
create_component "CreateComponent40"
remove_body "RemoveBody22"
create_component "CreateComponent41"
remove_body "RemoveBody23"
create_component "CreateComponent42"
create_component "CreateComponent1"
remove_body "RemoveBody24"
remove_body "RemoveBody25"
remove_body "RemoveBody26"
remove_body "RemoveBody27"
remove_body "RemoveBody28"
remove_body "RemoveBody29"
remove_body "RemoveBody30"
remove_body "RemoveBody31"
remove_body "RemoveBody32"
remove_body "RemoveBody33"
remove_body "RemoveBody34"
remove_body "RemoveBody35"
remove_body "RemoveBody36"
remove_body "RemoveBody37"
remove_body "RemoveBody38"
remove_body "RemoveBody39"
remove_body "RemoveBody40"
remove_body "RemoveBody41"
remove_body "RemoveBody42"
remove_body "RemoveBody43"
remove_body "RemoveBody44"
remove_body "RemoveBody45"
remove_body "RemoveBody46"
remove_body "RemoveBody47"
remove_body "RemoveBody48"
remove_body "RemoveBody49"
remove_body "RemoveBody50"
remove_body "RemoveBody51"
create_component "CreateComponent43"
create_component "CreateComponent1"
create_component "CreateComponent44"
create_component "CreateComponent1"
create_component "CreateComponent45"
create_component "CreateComponent1"
create_component "CreateComponent1"
create_component "CreateComponent2"
create_component "CreateComponent3"
create_component "CreateComponent7"
remove_body "RemoveBody4"
create_component "CreateComponent8"
remove_body "RemoveBody5"
create_component "CreateComponent9"
remove_body "RemoveBody6"
create_component "CreateComponent10"
create_component "CreateComponent1"
create_component "CreateComponent46"
create_component "CreateComponent47"
create_component "CreateComponent1"
named bodies: "Dogbones", "Dogbones (1)", "Dogbones (2)", "Dogbones (3)", "Dogbones (4)", "Dogbones (5)", "Dogbones (6)", "Dogbones (7)", "Dogbones (8)", "Dogbones (9)", "Dogbones (10)", "Dogbones (11)", "Dogbones (12)", "Dogbones (13)", "Dogbones (14)", "Dogbones (15)", "Dogbones (16)", "Dogbones (17)", "Dogbones1", "Dogbones1 (1)", "Dogbones1 (2)", "Dogbones1 (3)", "Dogbones1 (4)", "Dogbones (18)", "Dogbones1 (5)", "Dogbones1 (6)", "Dogbones (19)", "Dogbones (20)", "wall1", "wall0", "wall2", "Body1 (1)", "Body1 (1) (1)"

design "dollhome_wall_cnc" references "dollhome-final"
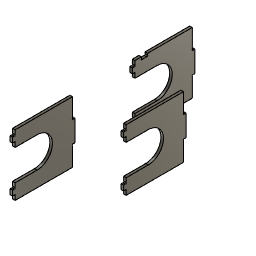
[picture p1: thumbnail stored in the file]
external_derived "ExternalDerived1" bodies "wall1", "wall0", "wall2"
derived_instance "DerivedInstance1"
derived_instance "DerivedInstance2"
derived_instance "DerivedInstance3"
base_feature "Base Feature1" bodies "Dogbones"
combine "Combine1"
base_feature "Base Feature2" bodies "Dogbones (1)"
combine "Combine1"
base_feature "Base Feature3" bodies "Dogbones (2)"
combine "Combine1"
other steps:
derived_base_feature "Derived Base Feature1" bodies "wall1"
derived_base_feature "Derived Base Feature1" bodies "wall0"
derived_base_feature "Derived Base Feature1" bodies "wall2"
create_component "CreateComponent1"
create_component "CreateComponent2"
create_component "CreateComponent3"
remove_body "RemoveBody1"
remove_body "RemoveBody2"
remove_body "RemoveBody3"
named bodies: "wall0", "wall1", "wall2", "Dogbones", "Dogbones (1)", "Dogbones (2)"

design "dollhome-final"
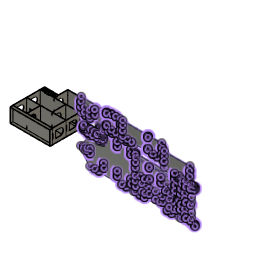
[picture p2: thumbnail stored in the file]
parameter "ply_Thickness" = 12
parameter "Clearance" = 0.1
parameter "length" = 830
parameter "width" = 300
parameter "Level_height" = 270
parameter "Kik" = 50
sketch "Sketch1" plane through (0, 0, 0) normal (0, 0, 1) x axis (1, 0, 0)
  line L1 (830, 0) -> (0, 0)
  line L2 (830, 908) -> (830, 0)
  line L3 (559.3333, 1097.5228) -> (830, 908)
  line L4 (288.6667, 908) -> (559.3333, 1097.5228)
  line L5 (288.6667, 716) -> (288.6667, 908)
  line L6 (0, 716) -> (288.6667, 716)
  line L7 (0, 0) -> (0, 716)
  line L8 (830, 908) -> (288.6667, 908)
  line L9 (830, 626) -> (0, 626)
  line L10 (830, 332) -> (0, 332)
  line L11 (830, 50) -> (0, 50)
  line L12 (830, 62) -> (0, 62)
  line L13 (830, 344) -> (0, 344)
  line L14 (830, 614) -> (0, 614)
  line L15 (830, 896) -> (288.6667, 896)
  line L16 (12, 0) -> (12, 716)
  line L17 (288.6667, 614) -> (288.6667, 716)
  line L18 (300.6667, 614) -> (300.6667, 908)
  line L19 (818, 0) -> (818, 908)
  line L20 (48.8889, 707) -> (30.4444, 707)
  line L21 (48.8889, 635) -> (48.8889, 707)
  line L22 (30.4444, 635) -> (48.8889, 635)
  line L23 (30.4444, 707) -> (30.4444, 635)
  line L24 (85.7778, 635) -> (85.7778, 707)
  line L25 (67.3333, 635) -> (85.7778, 635)
  line L26 (85.7778, 707) -> (67.3333, 707)
  line L27 (67.3333, 707) -> (67.3333, 635)
  line L28 (122.6667, 635) -> (122.6667, 707)
  line L29 (104.2222, 635) -> (122.6667, 635)
  line L30 (122.6667, 707) -> (104.2222, 707)
  line L31 (104.2222, 707) -> (104.2222, 635)
  line L32 (159.5556, 635) -> (159.5556, 707)
  line L33 (141.1111, 635) -> (159.5556, 635)
  line L34 (159.5556, 707) -> (141.1111, 707)
  line L35 (141.1111, 707) -> (141.1111, 635)
  line L36 (196.4444, 635) -> (196.4444, 707)
  line L37 (178, 635) -> (196.4444, 635)
  line L38 (196.4444, 707) -> (178, 707)
  line L39 (178, 707) -> (178, 635)
  line L40 (233.3333, 635) -> (233.3333, 707)
  line L41 (214.8889, 635) -> (233.3333, 635)
  line L42 (233.3333, 707) -> (214.8889, 707)
  line L43 (214.8889, 707) -> (214.8889, 635)
  line L44 (270.2222, 635) -> (270.2222, 707)
  line L45 (251.7778, 635) -> (270.2222, 635)
  line L46 (270.2222, 707) -> (251.7778, 707)
  line L47 (251.7778, 707) -> (251.7778, 635)
  line L48 (529.3333, 332) -> (529.3333, 626)
  line L49 (541.3333, 332) -> (541.3333, 626)
  line L50 (288.6667, 50) -> (288.6667, 344)
  line L51 (300.6667, 50) -> (300.6667, 344)
  line L52 (538.5833, 966.8214) -> (517.8333, 1002.7614)
  line L53 (580.0833, 966.8214) -> (538.5833, 966.8214)
  line L54 (600.8333, 1002.7614) -> (580.0833, 966.8214)
  line L55 (580.0833, 1038.7015) -> (600.8333, 1002.7614)
  line L56 (538.5833, 1038.7015) -> (580.0833, 1038.7015)
  line L57 (517.8333, 1002.7614) -> (538.5833, 1038.7015)
  line L58 (559.3333, 908) -> (559.3333, 1097.5228)
  line L59 (300.6667, 716) -> (288.6667, 716)
  line L60 (12, 671) -> (0, 671)
  line L61 (12, 685.4) -> (0, 685.4)
  line L62 (12, 656.6) -> (0, 656.6)
  line L63 (150.3333, 626) -> (150.3333, 716)
  line L64 (288.6667, 685.4) -> (300.6667, 685.4)
  line L65 (288.6667, 656.6) -> (300.6667, 656.6)
  line L66 (104.2222, 614) -> (104.2222, 626)
  line L67 (196.4444, 614) -> (196.4444, 626)
  line L68 (513.2222, 896) -> (513.2222, 908)
  line L69 (605.4444, 896) -> (605.4444, 908)
  line L70 (679.6667, 614) -> (679.6667, 626)
  line L71 (633.5556, 614) -> (633.5556, 626)
  line L72 (725.7778, 614) -> (725.7778, 626)
  line L73 (818, 479) -> (12, 479)
  line L74 (818, 197) -> (12, 197)
  line L75 (104.2222, 344) -> (104.2222, 332)
  line L76 (196.4444, 344) -> (196.4444, 332)
  line L77 (725.7778, 344) -> (725.7778, 332)
  line L78 (633.5556, 344) -> (633.5556, 332)
  line L79 (104.2222, 50) -> (104.2222, 62)
  line L80 (196.4444, 50) -> (196.4444, 62)
  line L81 (633.5556, 50) -> (633.5556, 62)
  line L82 (725.7778, 50) -> (725.7778, 62)
  line L83 (830, 761) -> (818, 761)
  line L84 (830, 807.1111) -> (818, 807.1111)
  line L85 (830, 714.8889) -> (818, 714.8889)
  line L86 (830, 150.8889) -> (818, 150.8889)
  line L87 (830, 243.1111) -> (818, 243.1111)
  line L88 (415, 62) -> (415, 332)
  line L89 (0, 243.1111) -> (12, 243.1111)
  line L90 (0, 150.8889) -> (12, 150.8889)
  line L91 (288.6667, 338) -> (0, 338)
  line L92 (0, 432.8889) -> (12, 432.8889)
  line L93 (0, 525.1111) -> (12, 525.1111)
  line L94 (288.6667, 807.1111) -> (300.6667, 807.1111)
  line L95 (288.6667, 714.8889) -> (300.6667, 714.8889)
  point P1 (0, 0)
  point P2 (0, 0)
  point P9 (0, 0)
  point P10 (0, 626)
  point P11 (830, 626)
  point P12 (0, 332)
  point P13 (830, 332)
  point P14 (0, 50)
  point P15 (830, 50)
  point P16 (0, 62)
  point P17 (830, 62)
  point P18 (0, 344)
  point P19 (830, 344)
  point P20 (0, 614)
  point P21 (830, 614)
  point P22 (288.6667, 896)
  point P23 (830, 896)
  point P24 (12, 716)
  point P25 (12, 0)
  point P26 (288.6667, 614)
  point P27 (300.6667, 908)
  point P28 (300.6667, 614)
  point P29 (818, 908)
  point P30 (818, 0)
  point P59 (529.3333, 626)
  point P60 (529.3333, 332)
  point P61 (541.3333, 626)
  point P62 (541.3333, 332)
  point P63 (288.6667, 344)
  point P64 (288.6667, 50)
  point P65 (300.6667, 344)
  point P66 (300.6667, 50)
  point P74 (559.3333, 908)
  point P73 (559.3333, 1002.7614)
  point P75 (300.6667, 716)
  point P76 (0, 671)
  point P77 (12, 671)
  point P78 (0, 685.4)
  point P79 (12, 685.4)
  point P80 (0, 656.6)
  point P81 (12, 656.6)
  point P83 (150.3333, 626)
  point P82 (150.3333, 716)
  point P84 (300.6667, 685.4)
  point P85 (288.6667, 685.4)
  point P86 (300.6667, 656.6)
  point P87 (288.6667, 656.6)
  point P88 (104.2222, 626)
  point P89 (104.2222, 614)
  point P90 (196.4444, 626)
  point P91 (196.4444, 614)
  point P92 (513.2222, 908)
  point P93 (513.2222, 896)
  point P94 (605.4444, 908)
  point P95 (605.4444, 896)
  point P96 (679.6667, 626)
  point P97 (679.6667, 614)
  point P98 (633.5556, 626)
  point P99 (633.5556, 614)
  point P100 (725.7778, 626)
  point P101 (725.7778, 614)
  point P102 (12, 479)
  point P103 (818, 479)
  point P104 (12, 197)
  point P105 (818, 197)
  point P106 (104.2222, 332)
  point P107 (104.2222, 344)
  point P108 (196.4444, 332)
  point P109 (196.4444, 344)
  point P112 (633.5556, 332)
  point P113 (633.5556, 344)
  point P110 (725.7778, 332)
  point P111 (725.7778, 344)
  point P114 (104.2222, 62)
  point P115 (104.2222, 50)
  point P116 (196.4444, 62)
  point P117 (196.4444, 50)
  point P120 (725.7778, 62)
  point P121 (725.7778, 50)
  point P118 (633.5556, 62)
  point P119 (633.5556, 50)
  point P122 (818, 761)
  point P123 (830, 761)
  point P124 (818, 807.1111)
  point P125 (830, 807.1111)
  point P126 (818, 714.8889)
  point P127 (830, 714.8889)
  point P128 (818, 150.8889)
  point P129 (830, 150.8889)
  point P130 (818, 243.1111)
  point P131 (830, 243.1111)
  point P132 (415, 332)
  point P133 (415, 62)
  point P136 (12, 150.8889)
  point P137 (0, 150.8889)
  point P134 (12, 243.1111)
  point P135 (0, 243.1111)
  point P138 (0, 338)
  point P139 (288.6667, 338)
  point P140 (12, 432.8889)
  point P141 (0, 432.8889)
  point P142 (12, 525.1111)
  point P143 (0, 525.1111)
  point P144 (300.6667, 807.1111)
  point P145 (288.6667, 807.1111)
  point P146 (300.6667, 714.8889)
  point P147 (288.6667, 714.8889)
  point P31 (30.4444, 707)
  point P32 (48.8889, 707)
  point P34 (30.4444, 635)
  point P68 (538.5833, 966.8214)
  point P69 (580.0833, 966.8214)
  coincident P1 P2
  horizontal L1
  perpendicular L1 L2
  parallel L2 L5
  perpendicular L5 L6
  coincident P1 P9
  perpendicular L1 L7
  perpendicular L2 L8
  coincident L7 P10
  coincident L2 P11
  perpendicular L2 L9
  coincident L7 P12
  coincident L2 P13
  perpendicular L2 L10
  coincident L7 P14
  coincident L2 P15
  perpendicular L2 L11
  coincident L7 P16
  coincident L2 P17
  perpendicular L2 L12
  coincident L7 P18
  coincident L2 P19
  perpendicular L2 L13
  coincident L7 P20
  coincident L2 P21
  perpendicular L2 L14
  coincident L5 P22
  coincident L2 P23
  perpendicular L2 L15
  coincident L6 P24
  coincident L1 P25
  perpendicular L1 L16
  coincident L14 P26
  perpendicular L14 L17
  coincident L8 P27
  coincident L14 P28
  perpendicular L14 L18
  coincident L8 P29
  coincident L1 P30
  perpendicular L1 L19
  horizontal L20
  vertical L21
  horizontal L22
  vertical L23
  coincident L9 P59
  coincident L10 P60
  perpendicular L10 L48
  coincident L9 P61
  coincident L10 P62
  perpendicular L10 L49
  coincident L13 P63
  coincident L11 P64
  perpendicular L11 L50
  coincident L13 P65
  coincident L11 P66
  perpendicular L11 L51
  midpoint L8 P74
  midpoint P73 L58
  horizontal L56
  coincident L18 P75
  perpendicular L18 L59
  coincident L7 P76
  coincident L16 P77
  perpendicular L16 L60
  coincident L7 P78
  coincident L16 P79
  perpendicular L16 L61
  coincident L7 P80
  coincident L16 P81
  perpendicular L16 L62
  symmetric L60 L61 L62
  coincident L9 P83
  perpendicular L9 L63
  coincident L6 P82
  symmetric P78 L63 P84
  symmetric P79 L63 P85
  symmetric P80 L63 P86
  symmetric P81 L63 P87
  coincident L9 P88
  coincident L14 P89
  perpendicular L14 L66
  coincident L9 P90
  coincident L14 P91
  perpendicular L14 L67
  symmetric L63 L66 L67
  coincident L8 P92
  coincident L15 P93
  perpendicular L15 L68
  coincident L8 P94
  coincident L15 P95
  perpendicular L15 L69
  coincident L9 P96
  coincident L14 P97
  perpendicular L14 L70
  coincident L9 P98
  coincident L14 P99
  perpendicular L14 L71
  coincident L9 P100
  coincident L14 P101
  perpendicular L14 L72
  symmetric L70 L71 L72
  coincident L16 P102
  coincident L19 P103
  perpendicular L19 L73
  symmetric L13 L14 L73
  coincident L16 P104
  coincident L19 P105
  perpendicular L19 L74
  symmetric L10 L12 L74
  symmetric P88 L73 P106
  symmetric P89 L73 P107
  symmetric P90 L73 P108
  symmetric P91 L73 P109
  symmetric P98 L73 P112
  symmetric P99 L73 P113
  symmetric P100 L73 P110
  symmetric P101 L73 P111
  symmetric L74 P106 P114
  symmetric L74 P107 P115
  symmetric L74 P108 P116
  symmetric L74 P109 P117
  symmetric L74 P110 P120
  symmetric L74 P111 P121
  symmetric L74 P112 P118
  symmetric L74 P113 P119
  coincident L19 P122
  coincident L2 P123
  perpendicular L2 L83
  coincident L19 P124
  coincident L2 P125
  perpendicular L2 L84
  coincident L19 P126
  coincident L2 P127
  perpendicular L2 L85
  symmetric L83 L84 L85
  symmetric L73 P124 P128
  symmetric L73 P125 P129
  symmetric L73 P126 P130
  symmetric L73 P127 P131
  midpoint L10 P132
  midpoint L12 P133
  symmetric P128 L88 P136
  symmetric P129 L88 P137
  symmetric P130 L88 P134
  symmetric P131 L88 P135
  coincident L7 P138
  coincident L50 P139
  perpendicular L50 L91
  symmetric L10 L13 L91
  symmetric P134 L91 P140
  symmetric P135 L91 P141
  symmetric P136 L91 P142
  symmetric P137 L91 P143
  symmetric L58 P124 P144
  symmetric L58 P125 P145
  symmetric L58 P126 P146
  symmetric L58 P127 P147
  dimension "d7" distance L7 L16 = 12 (= "ply_Thickness")
  dimension "d8" distance L10 L13 = 12 (= "d7")
  dimension "d9" distance L11 L12 = 12 (= "d7")
  dimension "d10" distance L2 L19 = 12 (= "d7")
  dimension "d11" distance L9 L14 = 12 (= "d7")
  dimension "d12" distance L17 L18 = 12 (= "d7")
  dimension "d13" distance L8 L15 = 12 (= "d7")
  dimension "d14" distance L2 L7 = 830 (= "length")
  dimension "d15" distance L10 L12 = 270 (= "Level_height")
  dimension "d16" distance L1 L11 = 50 (= "Kik")
  dimension "d17" distance L13 L14 = 270 (= "d15")
  dimension "d18" distance L9 L15 = 270 (= "d17")
  dimension "d19" angle L4 L8 = 35
  dimension "d21" distance L16 L17 = 276.6667 (= "d14 / 3")
  dimension "d22" distance L6 L9 = 90 (= "d18 / 3")
  dimension "d23" angle L3 L8 = 35 (= "d19")
  dimension "d25" distance P31 P32 = 18.4444 (= "d21 / 15")
  dimension "d26" distance L16 L23 = 18.4444 (= "d25")
  dimension "d27" distance P31 P34 = 72 (= "d22 * 0.8")
  dimension "d28" distance L9 L22 = 9 (= "d22 * 0.1")
  dimension "d33" distance L50 L51 = 12 (= "d7")
  dimension "d34" distance L48 L49 = 12 (= "d7")
  dimension "d35" distance L16 L50 = 276.6667 (= "d21")
  dimension "d36" distance L19 L49 = 276.6667 (= "d21")
  dimension "d37" distance P68 P69 = 41.5 (= "length * 0.05")
  dimension "d47" distance L61 L62 = 28.8 (= "d27 * 0.4")
  dimension "d48" distance L66 L67 = 92.2222 (= "d21 / 3")
  dimension "d49" distance L68 L69 = 92.2222 (= "d48")
  dimension "d50" distance L71 L72 = 92.2222 (= "d48")
  dimension "d53" distance L84 L85 = 92.2222 (= "d49")
  dimension "d31" R-Pattern1-uDistance = 36.8889 (= "( length / 3 ) / 15 * 2")
  dimension "d32" R-Pattern1-vDistance = 0
extrude "Extrude1" new body sketch "Sketch1" profile of L1 L2 L5 L6 L7 L8 L9 L10 L11 L12 L13 L14 L15 L16 L17 L18 L19 L48 L49 L50 L51 along normal blind 300 (= "width") bodies "wall2", "rightwall", "wall1", "leftwall", "wall0"
extrude "Extrude2" new body sketch "Sketch1" profile of L2 L5 L7 L8 L9 L10 L11 L12 L13 L14 L15 L16 L17 L18 L19 L48 L49 L50 L51 along normal blind 300 (= "width") bodies "roof", "lvl1", "lvl2", "lvl0"
extrude "Extrude4" sketch "Sketch1" profile of L6 L7 L9 L14 L16 L17 L18 L20 L21 L22 L23 L24 L25 L26 L27 L28 L29 L30 L31 L32 L33 L34 L35 L36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 no distance stored bodies "rail1"
extrude "Extrude3" new body sketch "Sketch1" profile of L1 L2 L3 L4 L5 L6 L7 L8 L9 L10 L11 L12 L13 L14 L15 L16 L17 L18 L19 L20 L21 L22 L23 L24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 along normal blind 12 (= "ply_Thickness") bodies "back"
combine "Combine1"
combine "Combine2"
combine "Combine3"
combine "Combine4"
combine "Combine5"
combine "Combine6"
combine "Combine7"
combine "Combine8"
combine "Combine9"
combine "Combine10"
combine "Combine11"
combine "Combine12"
